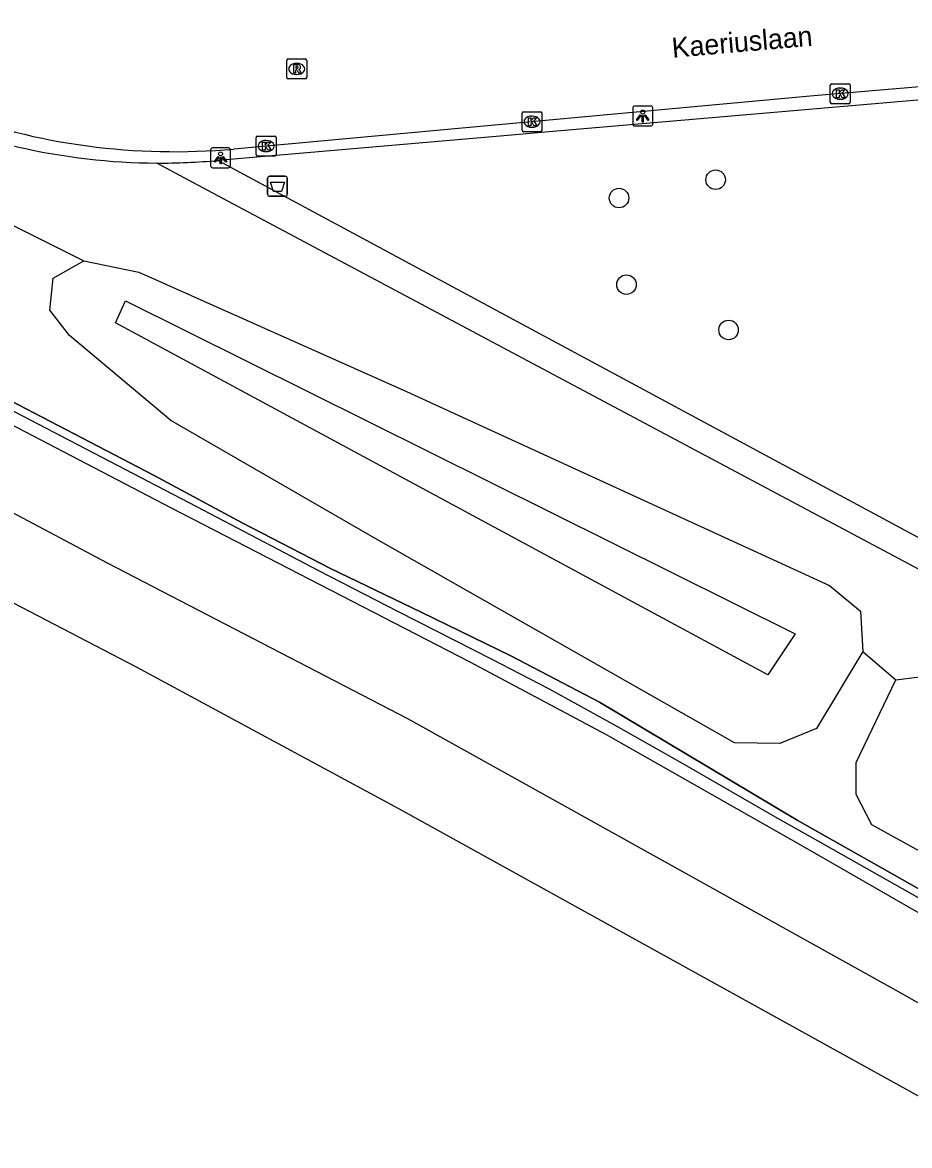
# Model space of a CAD drawing. Extents: x 162990 to 165007, y 383433 to 384336.
# Drawn here: x 164070.2 to 164114.7, y 383710.6 to 383766.8 of the extents above; entities that cross this region are included whole.
import ezdxf

# ---------------------------------------------------------------- set-up
doc = ezdxf.new("R2010")
doc.units = 0
for name, color, linetype in [('IMGEO_Afvalbak', 7, 'Continuous'), ('IMGEO_Boom', 7, 'Continuous'), ('IMGEO_Geluidsscherm', 7, 'Continuous'), ('IMGEO_Groenvoorziening', 7, 'Continuous'), ('IMGEO_Kolk', 7, 'Continuous'), ('IMGEO_Lichtpunt', 7, 'Continuous'), ('IMGEO_Openbare_ruimte_label', 7, 'Continuous'), ('IMGEO_Rijbaan_lokaal_open', 7, 'Continuous'), ('IMGEO_Rioolput', 7, 'Continuous'), ('IMGEO_Spoor', 7, 'Continuous'), ('IMGEO_Spoorbaan_halfverhard', 7, 'Continuous'), ('IMGEO_Voetpad_halfverhard', 7, 'Continuous'), ('IMGEO_Voetpad_open', 7, 'Continuous'), ('IMGEO_Waterloop', 7, 'Continuous')]:
    doc.layers.add(name, color=color, linetype=linetype)

msp = doc.modelspace()

# ---------------------------------------------------------------- linework, layer by layer
at = {"layer": 'IMGEO_Afvalbak'}
for p, q in [((164082.497, 383758.21), (164082.497, 383759.01)), ((164082.497, 383759.01), (164082.497, 383758.21)), ((164082.597, 383759.11), (164083.387, 383759.11)), ((164083.387, 383759.11), (164082.597, 383759.11)), ((164083.487, 383759.01), (164083.487, 383758.21)), ((164083.487, 383758.21), (164083.487, 383759.01)), ((164083.387, 383758.11), (164082.597, 383758.11)), ((164082.597, 383758.11), (164083.387, 383758.11))]:
    msp.add_line(p, q, dxfattribs=at)
msp.add_lwpolyline([(164082.64, 383758.824), (164083.344, 383758.824), (164083.195, 383758.354), (164082.789, 383758.354), (164082.64, 383758.824)], dxfattribs=at)
for centre, start, end in [((164082.597, 383759.01), 90, 180), ((164082.597, 383759.01), 90, 180), ((164083.387, 383759.01), 0, 90), ((164083.387, 383759.01), 360, 90), ((164082.597, 383758.21), 180, 270), ((164082.597, 383758.21), 180, 270), ((164083.387, 383758.21), 270, 0), ((164083.387, 383758.21), 270, 0)]:
    msp.add_arc(centre, 0.1, start, end, dxfattribs=at)
at = {"layer": 'IMGEO_Boom'}
for centre in [(164104.94, 383758.942), (164100.101, 383758.024), (164100.474, 383753.69), (164105.588, 383751.42)]:
    msp.add_circle(centre, 0.489, dxfattribs=at)
at = {"layer": 'IMGEO_Geluidsscherm'}
msp.add_lwpolyline([(164067.978, 383748.728), (164076.812, 383744.138), (164081.226, 383741.752), (164085.655, 383739.466), (164090.19, 383737.288), (164094.686, 383735.107), (164099.12, 383732.782), (164109.025, 383726.873), (164113.397, 383724.403), (164122.125, 383719.453), (164126.433, 383716.942), (164135.156, 383711.999), (164152.432, 383701.999), (164154.396, 383702.666), (164167.284, 383695.052)], dxfattribs=at)
at = {"layer": 'IMGEO_Groenvoorziening'}
for points in [[(164061.832, 383760.603), (164073.298, 383754.871)], [(164112.32, 383735.313), (164109.986, 383731.464), (164108.156, 383730.707), (164105.885, 383730.738), (164088.03, 383740.896), (164077.651, 383746.89), (164072.573, 383751.148), (164071.595, 383752.41), (164071.752, 383754.019), (164073.298, 383754.871)], [(164073.298, 383754.871), (164076.043, 383754.303), (164089.45, 383748.341), (164110.648, 383738.625), (164112.194, 383737.331), (164112.32, 383735.313)], [(164112.32, 383735.313), (164113.961, 383733.893)], [(164202.604, 383683.893), (164201.563, 383681.369), (164199.008, 383679.35), (164196.453, 383678.057), (164194.655, 383678.499), (164172.541, 383691.622), (164168.598, 383695.723), (164157.304, 383702.694), (164154.024, 383704.555), (164152.383, 383704.745), (164122.415, 383721.306), (164112.762, 383726.637), (164111.973, 383728.152), (164111.973, 383729.76), (164113.961, 383733.893)], [(164113.961, 383733.893), (164115.696, 383734.114), (164117.683, 383733.294), (164120.238, 383731.054), (164131.405, 383725.565), (164133.487, 383723.388), (164135.065, 383721.653), (164138.945, 383720.801), (164145.128, 383718.972), (164162.762, 383708.309), (164164.213, 383706.007), (164166.169, 383705.47), (164169.86, 383704.934), (164172.509, 383703.073), (164174.655, 383699.224), (164185.412, 383693.988), (164190.364, 383692.316), (164196.8, 383688.341), (164200.995, 383685.407), (164202.604, 383683.893)]]:
    msp.add_lwpolyline(points, dxfattribs=at)
at = {"layer": 'IMGEO_Kolk'}
for p, q in [((164110.756, 383763.748), (164111.608, 383763.748)), ((164110.681, 383762.822), (164110.681, 383763.674)), ((164111.169, 383763.528), (164111.194, 383763.528)), ((164111.682, 383763.674), (164111.682, 383762.822)), ((164111.608, 383762.748), (164110.756, 383762.748)), ((164111.192, 383762.968), (164111.167, 383762.968)), ((164095.242, 383761.418), (164095.242, 383762.27)), ((164095.317, 383762.344), (164096.169, 383762.344)), ((164095.73, 383762.124), (164095.755, 383762.124)), ((164096.243, 383762.27), (164096.243, 383761.418)), ((164095.753, 383761.564), (164095.728, 383761.564)), ((164081.925, 383760.2), (164081.925, 383761.052)), ((164082, 383761.126), (164082.852, 383761.126)), ((164082.413, 383760.906), (164082.438, 383760.906)), ((164082.926, 383761.052), (164082.926, 383760.2)), ((164096.169, 383761.344), (164095.317, 383761.344)), ((164082.436, 383760.346), (164082.411, 383760.346)), ((164082.852, 383760.126), (164082, 383760.126))]:
    msp.add_line(p, q, dxfattribs=at)
for points in [[(164110.756, 383763.748), (164111.608, 383763.748)], [(164110.681, 383762.822), (164110.681, 383763.674)], [(164111.002, 383763.448), (164111.125, 383763.448), (164111.125, 383763.297), (164111.255, 383763.448), (164111.419, 383763.448), (164111.273, 383763.297), (164111.426, 383763.048), (164111.274, 383763.048), (164111.189, 383763.212), (164111.125, 383763.145), (164111.125, 383763.048), (164111.002, 383763.048), (164111.002, 383763.448)], [(164111.682, 383763.674), (164111.682, 383762.822)], [(164111.608, 383762.748), (164110.756, 383762.748)], [(164095.242, 383761.418), (164095.242, 383762.27)], [(164095.317, 383762.344), (164096.169, 383762.344)], [(164095.563, 383762.044), (164095.686, 383762.044), (164095.686, 383761.893), (164095.816, 383762.044), (164095.98, 383762.044), (164095.834, 383761.893), (164095.987, 383761.644), (164095.835, 383761.644), (164095.75, 383761.808), (164095.686, 383761.741), (164095.686, 383761.644), (164095.563, 383761.644), (164095.563, 383762.044)], [(164096.243, 383762.27), (164096.243, 383761.418)], [(164081.925, 383760.2), (164081.925, 383761.052)], [(164082, 383761.126), (164082.852, 383761.126)], [(164082.926, 383761.052), (164082.926, 383760.2)], [(164096.169, 383761.344), (164095.317, 383761.344)], [(164082.246, 383760.826), (164082.369, 383760.826), (164082.369, 383760.675), (164082.499, 383760.826), (164082.663, 383760.826), (164082.517, 383760.675), (164082.67, 383760.426), (164082.518, 383760.426), (164082.433, 383760.59), (164082.369, 383760.523), (164082.369, 383760.426), (164082.246, 383760.426), (164082.246, 383760.826)], [(164082.852, 383760.126), (164082, 383760.126)]]:
    msp.add_lwpolyline(points, dxfattribs=at)
for centre, start, end in [((164110.758, 383763.672), 91.552, 178.448), ((164110.758, 383763.672), 91.552, 178.448), ((164111.606, 383763.672), 1.552, 88.448), ((164111.606, 383763.672), 1.552, 88.448), ((164110.758, 383762.824), 181.552, 268.448), ((164110.758, 383762.824), 181.552, 268.448), ((164111.606, 383762.824), 271.552, 358.448), ((164111.606, 383762.824), 271.552, 358.448), ((164095.319, 383762.268), 91.552, 178.448), ((164095.319, 383762.268), 91.552, 178.448), ((164096.167, 383762.268), 1.552, 88.448), ((164096.167, 383762.268), 1.552, 88.448), ((164082.002, 383761.05), 91.552, 178.448), ((164082.002, 383761.05), 91.552, 178.448), ((164082.85, 383761.05), 1.552, 88.448), ((164082.85, 383761.05), 1.552, 88.448), ((164095.319, 383761.42), 181.552, 268.448), ((164095.319, 383761.42), 181.552, 268.448), ((164096.167, 383761.42), 271.552, 358.448), ((164096.167, 383761.42), 271.552, 358.448), ((164082.002, 383760.202), 181.552, 268.448), ((164082.002, 383760.202), 181.552, 268.448), ((164082.85, 383760.202), 271.552, 358.448), ((164082.85, 383760.202), 271.552, 358.448)]:
    msp.add_arc(centre, 0.0765, start, end, dxfattribs=at)
for centre, major_axis, ratio, start_param, end_param in [((164111.168, 383763.248), (-0.387, 0.002), 0.722429, 4.712389, 7.853982), ((164111.193, 383763.248), (-0.39, 0.002), 0.717154, 1.570796, 4.712389), ((164095.729, 383761.844), (-0.387, 0.002), 0.722429, 4.712389, 7.853982), ((164095.754, 383761.844), (-0.39, 0.002), 0.717154, 1.570796, 4.712389), ((164082.412, 383760.626), (-0.387, 0.002), 0.722429, 4.712389, 7.853982), ((164082.437, 383760.626), (-0.39, 0.002), 0.717154, 1.570796, 4.712389)]:
    msp.add_ellipse(centre, major_axis=major_axis, ratio=ratio, start_param=start_param, end_param=end_param, dxfattribs=at)
at = {"layer": 'IMGEO_Lichtpunt'}
for p, q in [((164101.693, 383762.627), (164100.885, 383762.627)), ((164101.693, 383762.627), (164100.885, 383762.627)), ((164100.791, 383762.532), (164100.791, 383761.725)), ((164100.791, 383762.532), (164100.791, 383761.725)), ((164101.787, 383761.725), (164101.787, 383762.532)), ((164101.787, 383761.725), (164101.787, 383762.532)), ((164100.885, 383761.631), (164101.693, 383761.631)), ((164100.885, 383761.631), (164101.693, 383761.631)), ((164079.642, 383760.438), (164079.642, 383759.631)), ((164079.642, 383760.438), (164079.642, 383759.631)), ((164080.544, 383760.533), (164079.736, 383760.533)), ((164080.544, 383760.533), (164079.736, 383760.533)), ((164080.638, 383759.631), (164080.638, 383760.438)), ((164080.638, 383759.631), (164080.638, 383760.438)), ((164079.736, 383759.537), (164080.544, 383759.537)), ((164079.736, 383759.537), (164080.544, 383759.537))]:
    msp.add_line(p, q, dxfattribs=at)
for points in [[(164101.165, 383762.196), (164101.204, 383762.168), (164101.016, 383761.906), (164100.978, 383761.933), (164101.165, 383762.196)], [(164101.267, 383762.148), (164101.314, 383762.148), (164101.314, 383761.826), (164101.267, 383761.826), (164101.267, 383762.148)], [(164101.377, 383762.168), (164101.415, 383762.195), (164101.602, 383761.933), (164101.563, 383761.905), (164101.377, 383762.168)], [(164080.016, 383760.102), (164080.055, 383760.074), (164079.867, 383759.812), (164079.829, 383759.839), (164080.016, 383760.102)], [(164080.118, 383760.054), (164080.165, 383760.054), (164080.165, 383759.732), (164080.118, 383759.732), (164080.118, 383760.054)], [(164080.228, 383760.074), (164080.266, 383760.101), (164080.453, 383759.839), (164080.414, 383759.811), (164080.228, 383760.074)]]:
    msp.add_lwpolyline(points, dxfattribs=at)
for centre in [(164101.29, 383762.33), (164080.141, 383760.236)]:
    msp.add_circle(centre, 0.0994, dxfattribs=at)
for centre, start, end in [((164100.885, 383762.532), 90, 180), ((164100.885, 383762.532), 90, 180), ((164101.693, 383762.532), 0, 90), ((164101.693, 383762.532), 0, 90), ((164100.885, 383761.725), 180, 270), ((164100.885, 383761.725), 180, 270), ((164101.693, 383761.725), 270, 0), ((164101.693, 383761.725), 270, 360), ((164079.736, 383760.438), 90, 180), ((164079.736, 383760.438), 90, 180), ((164080.544, 383760.438), 0, 90), ((164080.544, 383760.438), 0, 90), ((164079.736, 383759.631), 180, 270), ((164079.736, 383759.631), 180, 270), ((164080.544, 383759.631), 270, 0), ((164080.544, 383759.631), 270, 360)]:
    msp.add_arc(centre, 0.0946, start, end, dxfattribs=at)
at = {"layer": 'IMGEO_Rijbaan_lokaal_open'}
msp.add_lwpolyline([(164121.439, 383764.129), (164109.867, 383763.137), (164080.8, 383760.478)], dxfattribs=at)
msp.add_arc((164077.837, 383793.286), 32.942, 249.6075, 275.1611, dxfattribs=at)
at = {"layer": 'IMGEO_Rioolput'}
for p, q in [((164083.455, 383764.062), (164083.455, 383764.914)), ((164083.53, 383764.988), (164084.382, 383764.988)), ((164084.456, 383764.914), (164084.456, 383764.062)), ((164083.943, 383764.768), (164083.968, 383764.768)), ((164084.382, 383763.988), (164083.53, 383763.988)), ((164083.966, 383764.208), (164083.941, 383764.208))]:
    msp.add_line(p, q, dxfattribs=at)
for points in [[(164083.455, 383764.062), (164083.455, 383764.914)], [(164083.53, 383764.988), (164084.382, 383764.988)], [(164084.456, 383764.914), (164084.456, 383764.062)], [(164084.044, 383764.686), (164083.792, 383764.688), (164083.792, 383764.288)], [(164083.792, 383764.288), (164083.916, 383764.288), (164083.916, 383764.45), (164083.927, 383764.45)], [(164083.97, 383764.607), (164083.916, 383764.607), (164083.916, 383764.526)], [(164083.916, 383764.526), (164083.968, 383764.526)], [(164083.974, 383764.421), (164084.045, 383764.288), (164084.185, 383764.288), (164084.12, 383764.414)], [(164084.382, 383763.988), (164083.53, 383763.988)]]:
    msp.add_lwpolyline(points, dxfattribs=at)
for centre, radius, start, end in [((164083.532, 383764.912), 0.0765, 91.552, 178.448), ((164083.532, 383764.912), 0.0765, 91.552, 178.448), ((164084.38, 383764.912), 0.0765, 1.552, 88.448), ((164084.38, 383764.912), 0.0765, 1.552, 88.448), ((164083.926, 383764.397), 0.0533, 26.0293, 88.6989), ((164083.952, 383764.715), 0.19, 274.7715, 282.9687), ((164083.976, 383764.511), 0.0964, 77.0061, 93.1865), ((164083.99, 383764.568), 0.0378, 276.6634, 79.6772), ((164084.043, 383764.576), 0.109, 350.3612, 89.416), ((164084.041, 383764.576), 0.112, 277.5842, 350.9817), ((164084.025, 383764.361), 0.108, 29.5134, 73.7905), ((164083.532, 383764.064), 0.0765, 181.552, 268.448), ((164083.532, 383764.064), 0.0765, 181.552, 268.448), ((164084.38, 383764.064), 0.0765, 271.552, 358.448), ((164084.38, 383764.064), 0.0765, 271.552, 358.448)]:
    msp.add_arc(centre, radius, start, end, dxfattribs=at)
for centre, major_axis, ratio, start_param, end_param in [((164083.942, 383764.488), (-0.387, 0.002), 0.722429, 4.712389, 7.853982), ((164083.967, 383764.488), (-0.39, 0.002), 0.717154, 1.570796, 4.712389)]:
    msp.add_ellipse(centre, major_axis=major_axis, ratio=ratio, start_param=start_param, end_param=end_param, dxfattribs=at)
at = {"layer": 'IMGEO_Spoor'}
for points in [[(163835.796, 383841.636), (163859.382, 383832.867), (163879.651, 383824.941), (163898.399, 383817.482), (163912.055, 383811.932), (163922.753, 383807.428), (163957.509, 383792.271), (163984.884, 383779.842), (164004.491, 383770.647), (164040.215, 383753.11), (164075.92, 383734.553), (164089.094, 383727.44), (164121.24, 383709.667), (164140.015, 383698.841), (164156.169, 383689.367), (164185.757, 383671.479), (164206.772, 383658.402), (164224.847, 383646.795), (164260.652, 383622.719), (164276.548, 383611.672), (164293.897, 383599.354), (164306.991, 383589.899), (164317.029, 383582.491), (164327.919, 383574.304)], [(163926.049, 383810.278), (163952.702, 383798.747), (163967.192, 383792.355), (163995.139, 383779.407), (164015.386, 383769.762), (164027.42, 383763.827), (164038.602, 383758.273), (164063.071, 383745.801), (164074.461, 383739.758), (164089.505, 383731.966), (164114.122, 383718.277), (164138.558, 383704.464), (164151.659, 383696.722), (164176.342, 383681.986), (164198.156, 383668.497), (164218.248, 383655.793), (164232.354, 383646.591), (164249.418, 383635.134), (164286.087, 383609.831), (164311.432, 383591.528), (164331.147, 383576.863)]]:
    msp.add_lwpolyline(points, dxfattribs=at)
at = {"layer": 'IMGEO_Spoorbaan_halfverhard'}
for points in [[(164135.524, 383710.553), (164124.919, 383716.617), (164118.829, 383720.101), (164109.323, 383725.548), (164099.479, 383731.146), (164092.611, 383734.808), (164077.684, 383742.488), (164059.94, 383751.749)], [(164065.81, 383749.41), (164078.944, 383742.585), (164085.042, 383739.371), (164089.042, 383737.325), (164093.736, 383734.931), (164096.569, 383733.46), (164099.961, 383731.599), (164103.268, 383729.721), (164108.046, 383726.973), (164109.67, 383726.051), (164115.438, 383722.791), (164124.25, 383717.716), (164132.932, 383712.76), (164138.81, 383709.402)], [(164167.284, 383695.052), (164154.396, 383702.666), (164152.432, 383701.999), (164135.156, 383711.999), (164126.433, 383716.942), (164122.125, 383719.453), (164113.397, 383724.403), (164109.025, 383726.873), (164099.12, 383732.782), (164094.686, 383735.107), (164090.19, 383737.288), (164085.655, 383739.466), (164081.226, 383741.752), (164076.812, 383744.138), (164067.978, 383748.728)]]:
    msp.add_lwpolyline(points, dxfattribs=at)
at = {"layer": 'IMGEO_Voetpad_halfverhard'}
for points in [[(164133.723, 383729.522), (164079.257, 383758.541), (164076.946, 383759.773)], [(164080.016, 383759.904), (164147.725, 383723.47)]]:
    msp.add_lwpolyline(points, dxfattribs=at)
at = {"layer": 'IMGEO_Voetpad_open'}
msp.add_lwpolyline([(164144.916, 383765.499), (164133.333, 383764.5), (164096.403, 383761.317), (164094.919, 383761.189), (164080.016, 383759.904)], dxfattribs=at)
for centre, radius, start, end in [((164077.126, 383791.382), 31.61, 244.4148, 269.6742), ((164077.066, 383792.988), 33.215, 269.7922, 275.0946)]:
    msp.add_arc(centre, radius, start, end, dxfattribs=at)
at = {"layer": 'IMGEO_Waterloop'}
msp.add_lwpolyline([(164107.558, 383734.156), (164074.877, 383751.773), (164075.388, 383752.88), (164108.92, 383736.199), (164107.558, 383734.156)], dxfattribs=at)

# ---------------------------------------------------------------- texts
at = {"layer": 'IMGEO_Openbare_ruimte_label'}
msp.add_text('Kaeriuslaan', height=1, rotation=4.935, dxfattribs=at).set_placement((164102.787, 383765.045))

doc.saveas('drawing.dxf')
